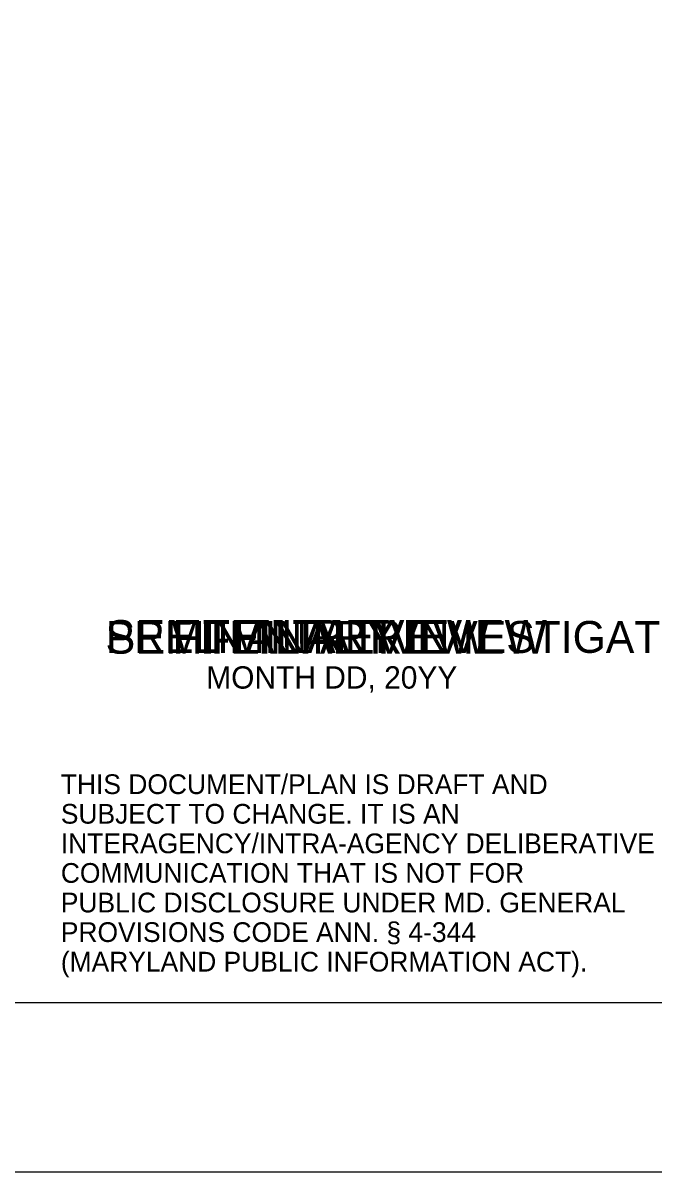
# Model space of a CAD drawing. Extents: x 0 to 34, y 0 to 22.
# Drawn here: x 24.64 to 27.44, y 0 to 5.09 of the extents above; entities that cross this region are included whole.
import ezdxf

# ---------------------------------------------------------------- set-up
doc = ezdxf.new("R2010")
doc.units = 0
for name, color, linetype in [('BORD-LINE', 7, 'Continuous'), ('STMP-FINA', 7, 'Continuous'), ('STMP-MPIA', 7, 'Continuous'), ('STMP-PRIN', 7, 'Continuous'), ('STMP-SEFI', 7, 'Continuous'), ('STMP-TENT', 7, 'Continuous'), ('USER-PAGE', 7, 'Continuous')]:
    doc.layers.add(name, color=color, linetype=linetype)

msp = doc.modelspace()

# ---------------------------------------------------------------- linework, layer by layer
at = {"layer": 'BORD-LINE'}
msp.add_lwpolyline([(1.5, 0.75), (33.5, 0.75), (33.5, 21.5), (1.5, 21.5)], close=True, dxfattribs=at)
at = {"layer": 'USER-PAGE'}
msp.add_lwpolyline([(0, 22), (34, 22), (34, 0), (0, 0)], close=True, dxfattribs=at)

# ---------------------------------------------------------------- texts
at = {"layer": 'STMP-FINA'}
for s, height, p in [('FINAL REVIEW', 0.1485, (25.3057, 2.2946)), ('MONTH DD, 20YY', 0.098999, (25.455, 2.1399))]:
    msp.add_text(s, height=height, dxfattribs=at).set_placement(p)
at = {"layer": 'STMP-MPIA'}
for s, p in [('THIS DOCUMENT/PLAN IS DRAFT AND', (24.812, 1.6732)), ('SUBJECT TO CHANGE. IT IS AN', (24.812, 1.5422)), ('INTERAGENCY/INTRA-AGENCY DELIBERATIVE', (24.812, 1.4113)), ('COMMUNICATION THAT IS NOT FOR', (24.812, 1.2803)), ('PUBLIC DISCLOSURE UNDER MD. GENERAL', (24.812, 1.1494)), ('PROVISIONS CODE ANN. § 4-344', (24.812, 1.0184)), ('(MARYLAND PUBLIC INFORMATION ACT).', (24.812, 0.8875))]:
    msp.add_text(s, height=0.0873, dxfattribs=at).set_placement(p)
at = {"layer": 'STMP-PRIN'}
for s, height, p in [('PRELIMINARY INVESTIGATION', 0.141075, (25.0106, 2.2983)), ('MONTH DD, 20YY', 0.098999, (25.455, 2.1399))]:
    msp.add_text(s, height=height, dxfattribs=at).set_placement(p)
at = {"layer": 'STMP-SEFI'}
for s, height, p in [('SEMI-FINAL REVIEW', 0.1485, (25.009, 2.2946)), ('MONTH DD, 20YY', 0.098999, (25.455, 2.1399))]:
    msp.add_text(s, height=height, dxfattribs=at).set_placement(p)
at = {"layer": 'STMP-TENT'}
for s, height, p in [('TENTATIVE', 0.1485, (25.4392, 2.2946)), ('MONTH DD, 20YY', 0.098999, (25.455, 2.1399))]:
    msp.add_text(s, height=height, dxfattribs=at).set_placement(p)

doc.saveas('drawing.dxf')
